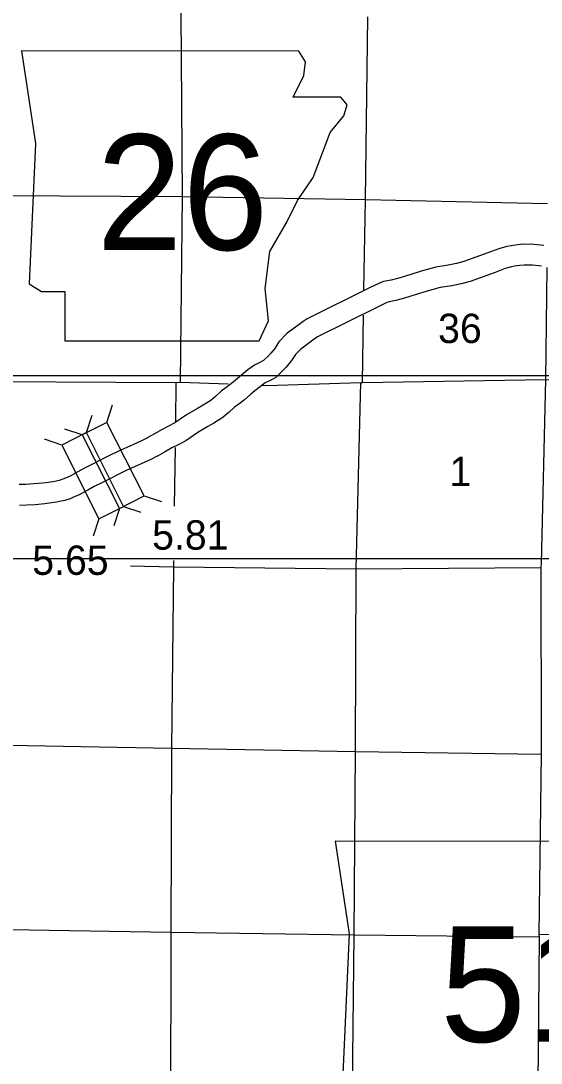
# Model space of a CAD drawing. Extents: x 369523 to 838377, y 495025 to 936819.
# Drawn here: x 501223 to 516206, y 742775 to 772794 of the extents above; entities that cross this region are included whole.
import ezdxf

# ---------------------------------------------------------------- set-up
doc = ezdxf.new("R2010")
doc.units = 0
for name, color, linetype in [('21', 7, 'Continuous'), ('22', 7, 'Continuous'), ('DSN_DRFT_Junk-No-Plot', 7, 'Continuous'), ('Level 1', 7, 'Continuous'), ('Level 15', 7, 'Continuous'), ('Level 21', 7, 'Continuous'), ('Level 22', 7, 'Continuous')]:
    doc.layers.add(name, color=color, linetype=linetype)

msp = doc.modelspace()

# ---------------------------------------------------------------- linework, layer by layer
at = {"layer": '21'}
for p, q in [((470439, 762579), (744999, 762579)), ((750279, 757299), (454599, 757299))]:
    msp.add_line(p, q, dxfattribs=at)
at = {"layer": '22'}
for points in [[(501245, 771927), (501645, 769263), (501467, 765222), (501822, 765000), (502488, 765000), (502488, 763578), (508084, 763578), (508350, 764156), (508262, 765088), (508395, 766154), (508883, 766998), (509194, 767620), (509638, 768286), (509905, 768996), (510127, 769574), (510526, 770062), (510615, 770373), (510438, 770595), (509061, 770595), (509372, 771217), (509416, 771617), (509232, 771923)], [(510274, 749165), (510674, 746501), (510496, 742460), (510852, 742237), (511518, 742237), (511518, 740816), (517113, 740816), (517380, 741394), (517291, 742326), (517424, 743392), (517913, 744236), (518223, 744858), (518668, 745524), (518934, 746234), (519156, 746812), (519556, 747300), (519645, 747611), (519467, 747833), (518090, 747833), (518401, 748455), (518446, 748854), (518261, 749161)]]:
    msp.add_lwpolyline(points, close=True, dxfattribs=at)
at = {"layer": 'Level 1'}
for p, q in [((504859, 760781), (504867, 760786)), ((505154, 760259), (505146, 760255))]:
    msp.add_line(p, q, dxfattribs=at)
for points in [[(516279, 766324), (515995, 766357), (515696, 766360), (515523, 766347), (515338, 766318), (515214, 766294), (514984, 766230), (514672, 766109), (513982, 765862), (513768, 765802), (513531, 765758), (513173, 765704), (512753, 765586), (512424, 765481), (512107, 765383), (511888, 765329), (511669, 765283), (511527, 765234), (511263, 765103), (509466, 764210), (509348, 764131), (509201, 764017), (508891, 763797), (508655, 763554), (508533, 763361), (508417, 763219), (508332, 763130), (508250, 763048), (508214, 763016), (508173, 762993), (508106, 762958), (507948, 762879), (507763, 762743), (507588, 762603), (507458, 762497), (507287, 762349), (507136, 762237), (506992, 762126), (506827, 761978), (506690, 761861), (506523, 761753)], [(516217, 765727), (515958, 765757), (515714, 765759), (515592, 765751), (515442, 765727), (515351, 765709), (515174, 765660), (514881, 765546), (514164, 765290), (513904, 765217), (513630, 765166), (513299, 765117), (512925, 765011), (512604, 764909), (512268, 764804), (512021, 764744), (511829, 764704), (511760, 764680), (511530, 764565), (509767, 763689), (509698, 763643), (509558, 763535), (509283, 763340), (509129, 763181), (509021, 763009), (508867, 762822), (508761, 762710), (508664, 762614), (508569, 762526), (508459, 762465), (508379, 762423), (508262, 762365), (508128, 762267), (507965, 762137), (507845, 762038), (507662, 761880), (507498, 761758), (507376, 761664), (507223, 761527), (507049, 761378), (506922, 761296)], [(506523, 761753), (506473, 761721), (506309, 761633), (505993, 761447), (505658, 761215), (505479, 761119), (505294, 761025), (505067, 760899), (504859, 760781)], [(506916, 761292), (506777, 761203), (506603, 761110), (506317, 760941), (505971, 760702), (505756, 760587), (505575, 760495), (505360, 760376), (505154, 760259)], [(504867, 760786), (504721, 760709), (504445, 760584), (504188, 760469), (503994, 760383), (503772, 760271), (503550, 760158), (503285, 760027), (503052, 759910), (502863, 759801), (502639, 759680), (502510, 759626), (502428, 759593), (502330, 759557), (502200, 759530)], [(505146, 760255), (504985, 760170), (504691, 760037), (504431, 759921), (504251, 759841), (504043, 759735), (503819, 759622), (503553, 759490), (503337, 759381), (503155, 759277), (502898, 759139), (502740, 759072), (502643, 759032), (502493, 758978), (502334, 758946)], [(501955, 759492), (501845, 759476), (501597, 759458), (501366, 759445), (501178, 759437)], [(502200, 759530), (502143, 759519), (501955, 759492)], [(502334, 758946), (502246, 758927), (501985, 758890)], [(501985, 758890), (501910, 758879), (501635, 758859), (501396, 758846), (501181, 758836)]]:
    msp.add_lwpolyline(points, dxfattribs=at)
at = {"layer": 'Level 15'}
for points in [[(516372, 765687), (516335, 762468), (516207, 757164), (516199, 757052), (516208, 751811), (516205, 751676), (516140, 746479), (516146, 746405), (516096, 741115), (516062, 739278)], [(489945, 762507), (495202, 762449), (495292, 762461), (500433, 762415), (500489, 762411), (505690, 762381), (505806, 762386), (507190, 762336)], [(508163, 762301), (508308, 762296), (511009, 762376), (511062, 762374), (516335, 762468), (521989, 762224), (522127, 762217), (527295, 762073), (527384, 762079)]]:
    msp.add_lwpolyline(points, dxfattribs=at)
at = {"layer": 'Level 21'}
for p, q in [((503698, 761229), (503863, 761731)), ((503112, 760934), (503278, 761435)), ((502992, 760871), (502490, 761035)), ((502404, 760578), (501903, 760744)), ((504773, 759110), (505275, 758946)), ((504066, 758752), (503902, 758250)), ((504179, 758811), (504680, 758645)), ((503471, 758455), (503305, 757954))]:
    msp.add_line(p, q, dxfattribs=at)
for points in [[(502992, 760871), (504066, 758752), (504773, 759110), (503698, 761229)], [(504179, 758811), (503112, 760934), (502404, 760578), (503471, 758455)]]:
    msp.add_lwpolyline(points, close=True, dxfattribs=at)
at = {"layer": 'Level 22'}
for points in [[(505826, 773041), (505868, 767726), (505806, 762386)], [(511103, 765051), (511143, 767642), (511213, 772906)], [(516392, 767528), (511143, 767642), (505868, 767726), (500583, 767751), (495246, 767768), (489956, 767837)], [(511062, 762374), (511092, 764322)], [(505690, 762381), (505674, 761250)], [(510730, 736570), (510763, 741170), (510824, 746460), (510858, 751754), (510883, 757013), (511009, 762376)], [(505663, 760503), (505639, 758820)], [(504384, 757101), (505614, 757065), (510883, 757013), (516199, 757052)], [(505616, 757248), (505614, 757065), (505561, 751849), (505545, 746534), (505534, 741280), (505468, 736004), (505454, 734664)], [(489806, 751923), (495117, 751897), (500348, 751947), (505561, 751849), (510858, 751754), (516205, 751676)], [(516146, 746405), (510824, 746460), (505545, 746534), (500286, 746625), (495057, 746589), (489788, 746674)], [(520305, 746426), (516140, 746479)]]:
    msp.add_lwpolyline(points, dxfattribs=at)

# ---------------------------------------------------------------- texts
at = {"layer": '22'}
for s, p in [('26', (503401, 766196)), ('51', (513295, 743389))]:
    msp.add_text(s, height=3326.4, dxfattribs=at).set_placement(p)
at = {"layer": 'DSN_DRFT_Junk-No-Plot'}
for s, p in [('5.81', (505003, 757565)), ('5.65', (501551, 756838))]:
    msp.add_text(s, height=844.8, dxfattribs=at).set_placement(p)
at = {"layer": 'Level 22'}
for s, height, p in [('36', 844.8, (513238, 763515)), ('1', 845, (513566, 759394))]:
    msp.add_text(s, height=height, dxfattribs=at).set_placement(p)

doc.saveas('drawing.dxf')
